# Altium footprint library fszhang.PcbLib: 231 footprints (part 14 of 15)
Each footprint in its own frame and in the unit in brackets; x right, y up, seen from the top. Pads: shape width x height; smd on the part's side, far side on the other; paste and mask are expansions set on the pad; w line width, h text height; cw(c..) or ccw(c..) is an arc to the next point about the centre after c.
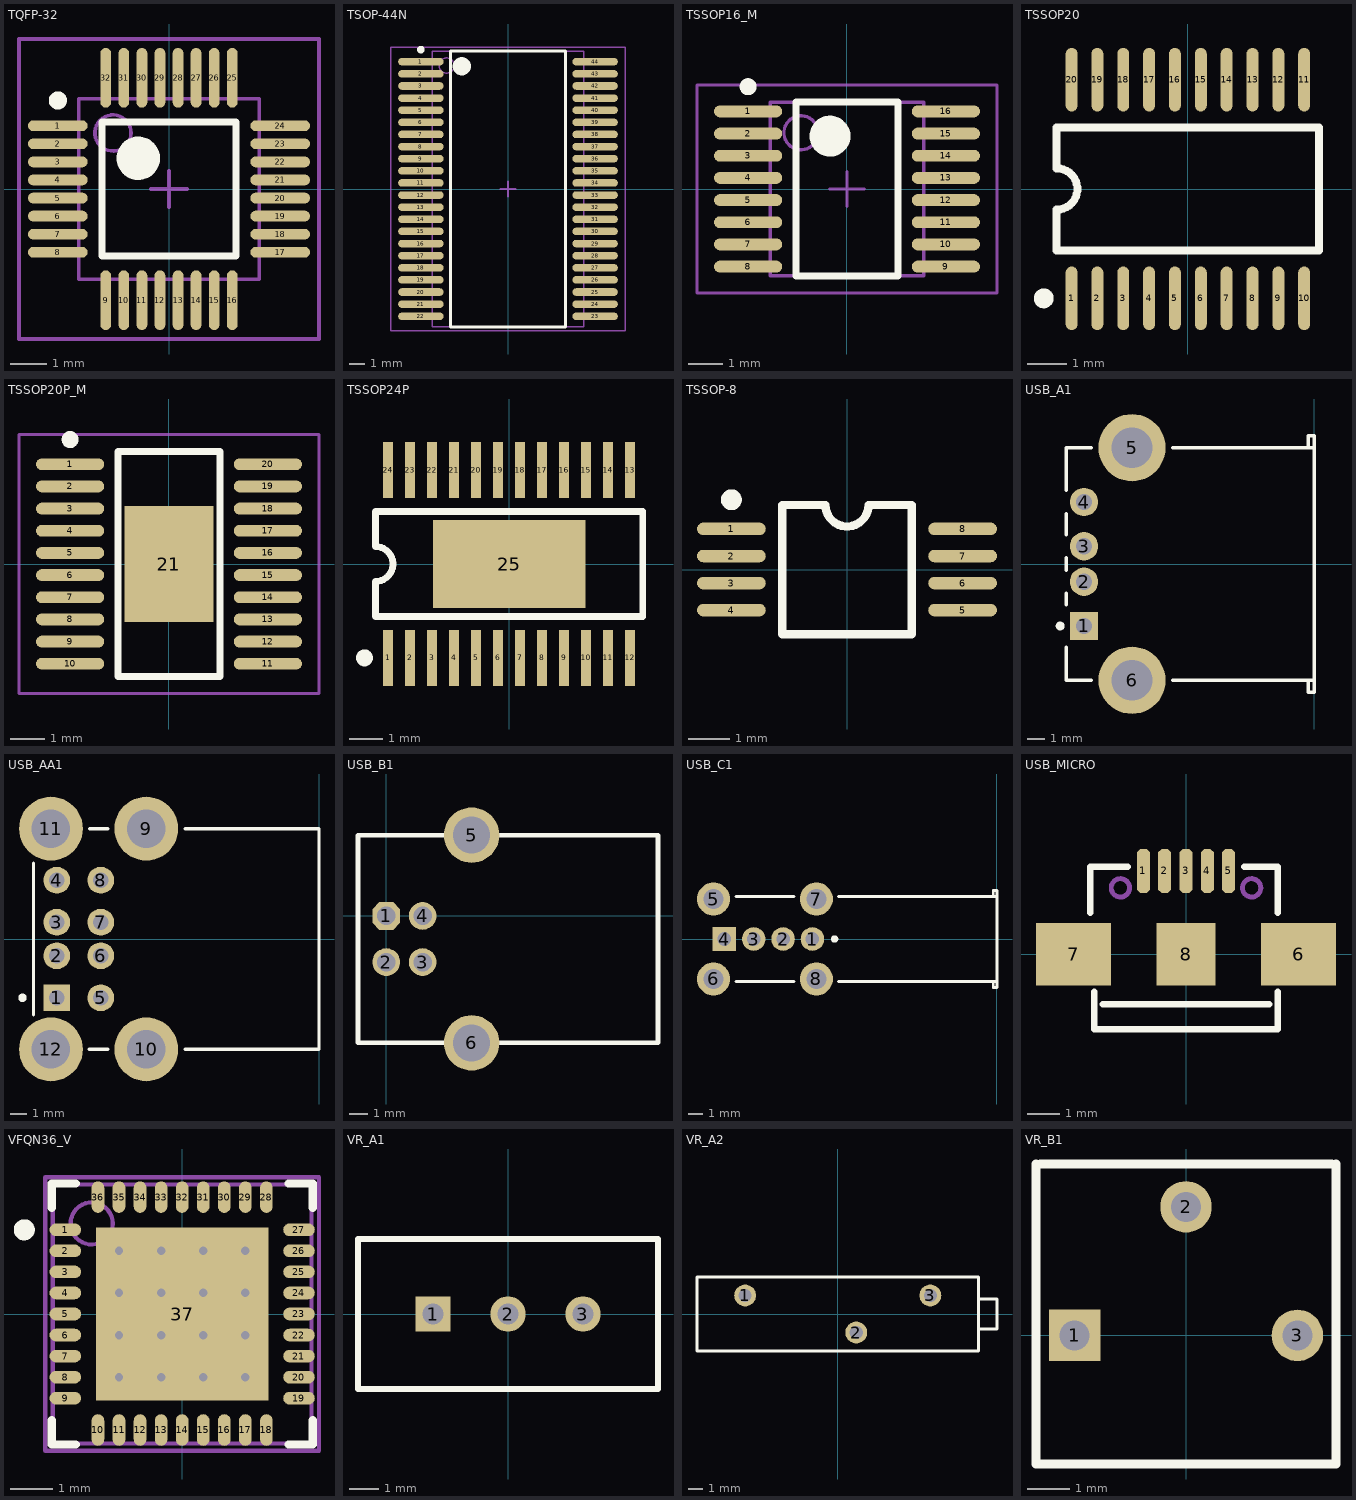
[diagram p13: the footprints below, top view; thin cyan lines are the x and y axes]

## TQFP-32 [mm]
height 1.2
pads (32):
  oval 1.65x0.3 smd: 1(-3.075,1.75) 2(-3.075,1.25) 3(-3.075,0.75) 4(-3.075,0.25) 5(-3.075,-0.25) 6(-3.075,-0.75) 7(-3.075,-1.25) 8(-3.075,-1.75) 17(3.075,-1.75) 18(3.075,-1.25) 19(3.075,-0.75) 20(3.075,-0.25) 21(3.075,0.25) 22(3.075,0.75) 23(3.075,1.25) 24(3.075,1.75)
  oval 0.3x1.65 smd: 9(-1.75,-3.075) 10(-1.25,-3.075) 11(-0.75,-3.075) 12(-0.25,-3.075) 13(0.25,-3.075) 14(0.75,-3.075) 15(1.25,-3.075) 16(1.75,-3.075) 25(1.75,3.075) 26(1.25,3.075) 27(0.75,3.075) 28(0.25,3.075) 29(-0.25,3.075) 30(-0.75,3.075) 31(-1.25,3.075) 32(-1.75,3.075)
Top Overlay:
  circle w0.6: c-0.85,0.85 r0.3
  circle w0.25: c-3.075,2.45 r0.125
  lines w0.2: -1.85,-1.85 1.85,-1.85 1.85,1.85 -1.85,1.85 -1.85,-1.85
Mechanical 13:
  circle w0.1: c-1.55,1.55 r0.5
  lines w0.1: -2.5,-2.5 2.5,-2.5 2.5,2.5 -2.5,2.5 -2.5,-2.5
Mechanical 15:
  lines w0.1: -0.5,0 0.5,0 ; 0,-0.5 0,0.5 ; -4.15,-4.15 4.15,-4.15 4.15,4.15 -4.15,4.15 -4.15,-4.15
3D body: height 1.2, standoff 0.1, extent -2.5,-2.5 2.5,2.5

## TSOP-44N [mm] "TSOP, 44-Leads, Body 18.2x10.0mm (max), Pitch 0.80mm, IPC Medium Density"
height 1.2
pads (44):
  oval 3x0.5 smd: 1(-5.75,8.4) 2(-5.75,7.6) 3(-5.75,6.8) 4(-5.75,6) 5(-5.75,5.2) 6(-5.75,4.4) 7(-5.75,3.6) 8(-5.75,2.8) 9(-5.75,2) 10(-5.75,1.2) 11(-5.75,0.4) 12(-5.75,-0.4) 13(-5.75,-1.2) 14(-5.75,-2) 15(-5.75,-2.8) 16(-5.75,-3.6) 17(-5.75,-4.4) 18(-5.75,-5.2) 19(-5.75,-6) 20(-5.75,-6.8) 21(-5.75,-7.6) 22(-5.75,-8.4) 23(5.75,-8.4) 24(5.75,-7.6) 25(5.75,-6.8) 26(5.75,-6) 27(5.75,-5.2) 28(5.75,-4.4) 29(5.75,-3.6) 30(5.75,-2.8) 31(5.75,-2) 32(5.75,-1.2) 33(5.75,-0.4) 34(5.75,0.4) 35(5.75,1.2) 36(5.75,2) 37(5.75,2.8) 38(5.75,3.6) 39(5.75,4.4) 40(5.75,5.2) 41(5.75,6) 42(5.75,6.8) 43(5.75,7.6) 44(5.75,8.4)
Top Overlay:
  circle w0.25: c-5.75,9.2 r0.125
  circle w0.6: c-3.05,8.1 r0.3
  lines w0.2: -3.81,-9.1 -3.81,9.1 3.81,9.1 3.81,-9.1 -3.81,-9.1
Mechanical 13:
  circle w0.1: c-4.05,8.15 r0.5
  lines w0.1: -5,-9.1 -5,9.1 5,9.1 5,-9.1 -5,-9.1
Mechanical 15:
  lines w0.1: -0.5,0 0.5,0 ; 0,-0.5 0,0.5 ; -7.747,-9.35 -7.747,9.35 7.747,9.35 7.747,-9.35 -7.747,-9.35
3D body: height 1.2, standoff 0.2, extent -5,-9.1 5,9.1

## TSSOP16_M [mm] "TSOP, 16-Leads, Body 5x4.4mm, Pitch 0.65mm, IPC Low Density"
height 1.1
pads (16):
  oval 2x0.35 smd: 1(-2.9,2.275) 2(-2.9,1.625) 3(-2.9,0.975) 4(-2.9,0.325) 5(-2.9,-0.325) 6(-2.9,-0.975) 7(-2.9,-1.625) 8(-2.9,-2.275) 9(2.9,-2.275) 10(2.9,-1.625) 11(2.9,-0.975) 12(2.9,-0.325) 13(2.9,0.325) 14(2.9,0.975) 15(2.9,1.625) 16(2.9,2.275)
Top Overlay:
  circle w0.6: c-0.5,1.55 r0.3
  circle w0.25: c-2.9,3 r0.125
  lines w0.2: -1.5,-2.55 1.5,-2.55 1.5,2.55 -1.5,2.55 -1.5,-2.55
Mechanical 13:
  circle w0.1: c-1.35,1.65 r0.5
  lines w0.1: -2.25,-2.55 2.25,-2.55 2.25,2.55 -2.25,2.55 -2.25,-2.55
Mechanical 15:
  lines w0.1: -0.5,0 0.5,0 ; 0,-0.5 0,0.5 ; -4.4,-3.05 4.4,-3.05 4.4,3.05 -4.4,3.05 -4.4,-3.05
3D body: height 1.1, standoff 0, extent -2.25,-2.55 2.25,2.55

## TSSOP20 [mm] "Shrink Small Outline; 20 Leads; Body Width 4.4 mm; Pitch 0.65 mm"
height 1.1
pads (20):
  oval 0.3x1.6 smd: 1(-2.925,-2.75) 2(-2.275,-2.75) 3(-1.625,-2.75) 4(-0.975,-2.75) 5(-0.325,-2.75) 6(0.325,-2.75) 7(0.975,-2.75) 8(1.625,-2.75) 9(2.275,-2.75) 10(2.925,-2.75) 11(2.925,2.75) 12(2.275,2.75) 13(1.625,2.75) 14(0.975,2.75) 15(0.325,2.75) 16(-0.325,2.75) 17(-0.975,2.75) 18(-1.625,2.75) 19(-2.275,2.75) 20(-2.925,2.75)
Top Overlay:
  circle w0.25: c-3.625,-2.75 r0.125
  lines w0.2: -3.3,-1.55 -3.3,-0.52 ccw(c-3.3,0) -3.3,0.52 -3.3,1.55 3.3,1.55 3.3,-1.55 -3.3,-1.55
3D body: height 1.1, standoff 0, extent -3.302,-1.905 3.302,1.905

## TSSOP20P_M [mm] "TSOP, 20-Leads, Body 6.5x4.4mm, Pitch 0.65mm, IPC Low Density"
height 1.1
pads (21):
  oval 2x0.35 smd: 1(-2.9,2.925) 2(-2.9,2.275) 3(-2.9,1.625) 4(-2.9,0.975) 5(-2.9,0.325) 6(-2.9,-0.325) 7(-2.9,-0.975) 8(-2.9,-1.625) 9(-2.9,-2.275) 10(-2.9,-2.925) 11(2.9,-2.925) 12(2.9,-2.275) 13(2.9,-1.625) 14(2.9,-0.975) 15(2.9,-0.325) 16(2.9,0.325) 17(2.9,0.975) 18(2.9,1.625) 19(2.9,2.275) 20(2.9,2.925)
  rect 2.6x3.4 smd: 21(0,0)
Top Overlay:
  circle w0.25: c-2.9,3.65 r0.125
  lines w0.2: -1.5,-3.3 -1.5,3.3 1.5,3.3 1.5,-3.3 -1.5,-3.3
Mechanical 15:
  lines w0.1: -4.4,-3.8 -4.4,3.8 4.4,3.8 4.4,-3.8 -4.4,-3.8

## TSSOP24P [mm] "Shrink Small Outline; 24 Leads; Body Width 4.4 mm; Pitch 0.65 mm"
height 1.2
pads (25):
  rect 0.3x1.65 smd: 1(-3.575,-2.775) 2(-2.925,-2.775) 3(-2.275,-2.775) 4(-1.625,-2.775) 5(-0.975,-2.775) 6(-0.325,-2.775) 7(0.325,-2.775) 8(0.975,-2.775) 9(1.625,-2.775) 10(2.275,-2.775) 11(2.925,-2.775) 12(3.575,-2.775) 13(3.575,2.775) 14(2.925,2.775) 15(2.275,2.775) 16(1.625,2.775) 17(0.975,2.775) 18(0.325,2.775) 19(-0.325,2.775) 20(-0.975,2.775) 21(-1.625,2.775) 22(-2.275,2.775) 23(-2.925,2.775) 24(-3.575,2.775)
  rect 4.5x2.6 smd: 25(0,0)
Top Overlay:
  circle w0.25: c-4.275,-2.775 r0.125
  lines w0.2: -3.95,-1.55 3.95,-1.55 3.95,1.55 -3.95,1.55 -3.95,0.517 cw(c-3.95,0) -3.95,-0.517 -3.95,-1.55

## TSSOP-8 [mm]
height 0.8
pads (8):
  oval 1.65x0.3 smd: 1(-2.775,0.975) 2(-2.775,0.325) 3(-2.775,-0.325) 4(-2.775,-0.975) 5(2.775,-0.975) 6(2.775,-0.325) 7(2.775,0.325) 8(2.775,0.975)
Top Overlay:
  circle w0.25: c-2.775,1.675 r0.125
  lines w0.2: -1.55,-1.55 1.55,-1.55 1.55,1.55 0.517,1.55 cw(c0,1.55) -0.517,1.55 -1.55,1.55 -1.55,-1.55

## USB_A1 [mm]
height 7.01
pads (6):
  rect 1.6x1.6 hole 0.92: 1(-12.99,-3.5)
  round 1.6 hole 0.92: 2(-12.99,-1) 3(-12.99,1) 4(-12.99,3.5)
  round 3.8 hole 2.3: 5(-10.28,6.57) 6(-10.28,-6.57)
Top Overlay:
  circle w0.25: c-14.34,-3.5 r0.125
  lines w0.2: -14,-4.7 -14,-6.565 -12.58,-6.565 ; -14,-2.3 -14,-1.66 ; -14,-0.34 -14,0.34 ; -14,1.66 -14,2.84 ; -14,4.16 -14,6.565 -12.58,6.565 ; -7.98,-6.565 0,-6.565 ; -7.98,6.565 0,6.565 ; -0.32,-6.565 -0.32,-7.25 0,-7.25 0,-6.565 ; -0.32,6.565 -0.32,7.25 0,7.25 0,6.565 ; 0,-6.565 0,6.565

## USB_AA1 [mm] "USB母座A型"
height 15.51
pads (12):
  rect 1.6x1.6 hole 0.92: 1(-15.61,-3.5)
  round 1.6 hole 0.92: 2(-15.61,-1) 3(-15.61,1) 4(-15.61,3.5) 5(-12.99,-3.5) 6(-12.99,-1) 7(-12.99,1) 8(-12.99,3.5)
  round 3.8 hole 2.3: 9(-10.28,6.57) 10(-10.28,-6.57) 11(-15.96,6.57) 12(-15.96,-6.57)
Top Overlay:
  circle w0.25: c-17.65,-3.5 r0.125
  lines w0.2: -17,-4.51 -17,4.51 ; -13.68,-6.565 -12.58,-6.565 ; -13.66,6.565 -12.58,6.565 ; -7.97,-6.565 0,-6.565 0,6.565 -7.97,6.565

## USB_B1 [mil] "USB方孔"
height 314.96
pads (6):
  oct 60x60 hole 40: 1(0,0)
  round 60 hole 40: 2(0,-100) 3(78.74,-100) 4(78.74,0)
  round 120 hole 80: 5(185.04,175) 6(185.04,-275)
Top Overlay:
  lines w10: -61.26,-275 -61.26,175 588.74,175 588.74,-275 -61.26,-275

## USB_C1 [mm] "侧卧USB"
height 13.83
pads (8):
  round 1.6 hole 0.92: 1(-12.56,0) 2(-14.56,0) 3(-16.56,0)
  rect 1.6x1.6 hole 0.92: 4(-18.56,0)
  round 2.25 hole 1.35: 5(-19.29,2.72) 6(-19.29,-2.72) 7(-12.29,2.72) 8(-12.29,-2.72)
Top Overlay:
  circle w0.25: c-11.047,0 r0.125
  lines w0.2: -17.773,-2.88 -13.807,-2.88 ; -17.773,2.88 -13.807,2.88 ; -10.773,-2.88 0,-2.88 ; -10.773,2.88 0,2.88 ; -0.254,-2.88 -0.254,-3.302 0,-3.302 0,-2.88 ; -0.254,2.88 -0.254,3.302 0,3.302 0,2.88 ; 0,-2.88 0,2.88

## USB_MICRO [mm] "USB方孔"
height 8
pads (8):
  oct 0.4x1.35 smd: 1(-1.3,2.54) 2(-0.65,2.54) 3(0,2.54) 4(0.65,2.54) 5(1.3,2.54)
  rect 2.286x1.9 smd: 6(3.429,0) 7(-3.429,0)
  rect 1.8x1.9 smd: 8(0,0)
Top Overlay:
  lines w0.2: -2.921,1.27 -2.921,2.667 -1.778,2.667 ; -2.794,-1.143 -2.794,-2.286 2.794,-2.286 2.794,-1.143 ; -2.54,-1.524 2.54,-1.524 ; 1.778,2.667 2.794,2.667 2.794,1.27
Mechanical 1:
  circle w0.15: c-2,2.023 r0.28
  circle w0.15: c2,2.023 r0.28

## VFQN36_V [mm] "QFN, 36-Leads, Body 6x6mm, Pitch 0.5mm, ST Recommended"
height 1
pads (37):
  oval 0.75x0.3 smd: 1(-2.775,2) 2(-2.775,1.5) 3(-2.775,1) 4(-2.775,0.5) 5(-2.775,0) 6(-2.775,-0.5) 7(-2.775,-1) 8(-2.775,-1.5) 9(-2.775,-2) 19(2.775,-2) 20(2.775,-1.5) 21(2.775,-1) 22(2.775,-0.5) 23(2.775,0) 24(2.775,0.5) 25(2.775,1) 26(2.775,1.5) 27(2.775,2)
  oval 0.3x0.75 smd: 10(-2,-2.755) 11(-1.5,-2.755) 12(-1,-2.755) 13(-0.5,-2.755) 14(0,-2.755) 15(0.5,-2.755) 16(1,-2.755) 17(1.5,-2.755) 18(2,-2.755) 28(2,2.775) 29(1.5,2.775) 30(1,2.775) 31(0.5,2.775) 32(0,2.775) 33(-0.5,2.775) 34(-1,2.775) 35(-1.5,2.775) 36(-2,2.775)
  rect 4.1x4.1 smd: 37(0,0)
via -1.5,1.5 diameter 0.4 hole 0.2
via -0.5,1.5 diameter 0.4 hole 0.2
via 0.5,1.5 diameter 0.4 hole 0.2
via 1.5,1.5 diameter 0.4 hole 0.2
via -1.5,0.5 diameter 0.4 hole 0.2
via -0.5,0.5 diameter 0.4 hole 0.2
via 0.5,0.5 diameter 0.4 hole 0.2
via 1.5,0.5 diameter 0.4 hole 0.2
via -1.5,-0.5 diameter 0.4 hole 0.2
via -0.5,-0.5 diameter 0.4 hole 0.2
via 0.5,-0.5 diameter 0.4 hole 0.2
via 1.5,-0.5 diameter 0.4 hole 0.2
via -1.5,-1.5 diameter 0.4 hole 0.2
via -0.5,-1.5 diameter 0.4 hole 0.2
via 0.5,-1.5 diameter 0.4 hole 0.2
via 1.5,-1.5 diameter 0.4 hole 0.2
Top Overlay:
  circle w0.25: c-3.75,2 r0.125
  lines w0.2: -3.1,-2.525 -3.1,-3.1 -2.525,-3.1 ; -3.1,2.525 -3.1,3.1 -2.525,3.1 ; 2.525,-3.1 3.1,-3.1 3.1,-2.525 ; 2.525,3.1 3.1,3.1 3.1,2.525
Mechanical 13:
  circle w0.1: c-2.15,2.15 r0.5
  lines w0.1: -3.075,3.05 -3.075,-3.075 3.075,-3.075 3.075,3.075 -3.075,3.075
Mechanical 15:
  lines w0.1: -0.5,0 0.5,0 ; 0,-0.5 0,0.5 ; -3.25,-3.25 -3.25,3.25 3.25,3.25 3.25,-3.25 -3.25,-3.25
3D body: height 1, standoff 0, extent -3.05,-3.05 3.05,3.05

## VR_A1 [mm] "Potentiometer; 3 Leads"
height 1.1
pads (3):
  rect 1.2x1.2 hole 0.7: 1(-2.54,0)
  round 1.2 hole 0.7: 2(0,0) 3(2.54,0)
Top Overlay:
  lines w0.2: -5.08,-2.54 5.08,-2.54 5.08,0 5.08,2.54 -5.08,2.54 -5.08,-2.54
3D body: height 10.5, standoff 10, extent 3.301,-1.765 4.337,-0.729
3D body: height 10, standoff 0, extent -5.08,-2.54 5.08,2.54

## VR_A2 [mm]
height 6.5
pads (3):
  round 1.5 hole 0.9: 1(-6.35,1.27) 2(1.27,-1.27) 3(6.35,1.27)
Top Overlay:
  lines w0.2: 9.652,-1.016 10.922,-1.016 10.922,1.016 9.652,1.016 ; -9.652,-2.54 9.652,-2.54 9.652,2.54 -9.652,2.54 -9.652,-2.54

## VR_B1 [mm] "Potentiometer; 3 Leads"
height 12
pads (3):
  rect 1.2x1.2 hole 0.7: 1(-2.6,0)
  round 1.2 hole 0.7: 2(0,3) 3(2.6,0)
Top Overlay:
  lines w0.2: -3.5,4 -3.5,-3 3.5,-3 3.5,4 ; -3.4,4 3.4,4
